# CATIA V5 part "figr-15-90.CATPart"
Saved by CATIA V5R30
Part number: Part1
Bounding box of the stored display mesh (mm): x -45.183 to 59.676, y -22.214 to 29.903, z -4 to 1
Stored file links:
  D:\PROJECTS\CATIA V56R 2020\Resources\Parts File\c15_catia_v5_6r2020_prt\figr-15-90.CATPart
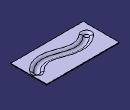
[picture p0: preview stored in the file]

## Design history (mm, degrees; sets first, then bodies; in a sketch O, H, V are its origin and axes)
SheetMetalParameters1: Thickness 1, BendRadius 5, KFactor 0.5 {= log(min(100,max(20*SheetMetalParameters1.BendRadius,SheetMetalParameters1.Thickness)/SheetMetalParameters1.Thickness))/log(100)/2}, ReliefRadialLength 1, ReliefAxialLength 2, MinimumBendRadius 0
Body1 (main body)
  Sketch1 on xy-plane, origin (0, 0, 0), H (1, 0, 0), V (0, 1, 0)
    line L1 (-45.1833, 29.903) -> (59.6761, 29.903)
    line L2 (59.6761, 29.903) -> (59.6761, -22.2137)
    line L3 (59.6761, -22.2137) -> (-45.1833, -22.2137)
    line L4 (-45.1833, -22.2137) -> (-45.1833, 29.903)
    horizontal: L1 H, L3 H
    vertical: L2 V, L4 V
  Wall1: Thickness 1, Profile Sketch1
  Sketch2 on face of Wall1, origin (0, 0, 1), H (1, 0, 0), V (0, 1, 0)
    spline S1 through (-31.3214, -3.7025) (-6.2947, 5.2247) (29.3365, -3.7025) (50.9697, 6.9251)
  d_Stamp1: Stamp_FilletRadius 4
